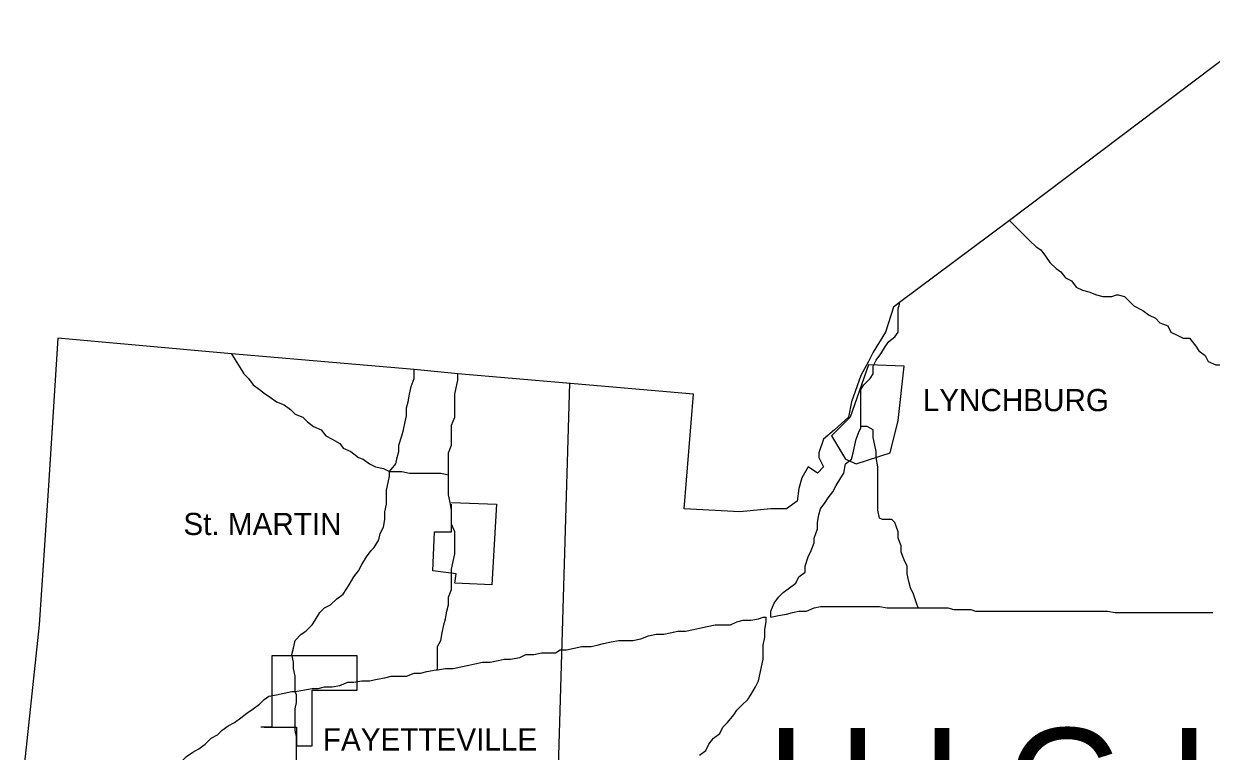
# Model space of a CAD drawing. Extents: x 0 to 34, y 0 to 22.
# Drawn here: x 2.524 to 3.569, y 18.392 to 19.032 of the extents above; entities that cross this region are included whole.
import ezdxf

# ---------------------------------------------------------------- set-up
doc = ezdxf.new("R2010")
doc.units = 0
doc.layers.add('Default', color=7, linetype='Continuous')
doc.layers.add('TR_Turning_Path1', color=7, linetype='Continuous')

msp = doc.modelspace()

# ---------------------------------------------------------------- linework, layer by layer
at = {"layer": 'Default'}
for points in [[(3.6203, 19.0319), (3.3913, 18.8587), (3.2945, 18.7865), (3.289, 18.7824), (3.2822, 18.7606), (3.2713, 18.7428), (3.2672, 18.7347), (3.2604, 18.7224), (3.2522, 18.6992), (3.2495, 18.6856), (3.2372, 18.6747), (3.2277, 18.6665), (3.2236, 18.6542), (3.2236, 18.6501), (3.2277, 18.6419), (3.2222, 18.6365), (3.214, 18.6419), (3.2086, 18.6324), (3.2059, 18.6229), (3.2045, 18.6119), (3.195, 18.6051), (3.1813, 18.6051), (3.1541, 18.6024), (3.105, 18.6051), (3.1132, 18.706), (3.0014, 18.7156)], [(3.3913, 18.8587), (3.3954, 18.8546), (3.4008, 18.8492), (3.4049, 18.8451), (3.409, 18.841), (3.4145, 18.8355), (3.4186, 18.8328), (3.4227, 18.8274), (3.4267, 18.8219), (3.4322, 18.8165), (3.4363, 18.8137), (3.4404, 18.8083), (3.4458, 18.8056), (3.4499, 18.8001), (3.4554, 18.7974), (3.4608, 18.796), (3.4676, 18.7933), (3.4731, 18.7919), (3.4813, 18.7919), (3.4854, 18.7933), (3.4867, 18.7933)], [(3.4867, 18.7933), (3.4922, 18.7919), (3.4976, 18.7865), (3.5004, 18.7837), (3.5085, 18.7796), (3.514, 18.7756), (3.5195, 18.7728), (3.5235, 18.7687), (3.5304, 18.766), (3.5331, 18.7606), (3.5385, 18.7578), (3.544, 18.7551), (3.5494, 18.7551), (3.5549, 18.7483), (3.5576, 18.7442), (3.5631, 18.7401), (3.5658, 18.7347), (3.5726, 18.7319), (3.5794, 18.7319), (3.5849, 18.7319), (3.5876, 18.7319), (3.589, 18.7319)], [(3.2604, 18.6774), (3.2604, 18.6828), (3.2604, 18.6897), (3.2604, 18.6965), (3.2604, 18.7019), (3.2604, 18.7101), (3.2631, 18.7142), (3.2686, 18.7197), (3.2713, 18.7237), (3.2713, 18.7306), (3.274, 18.736), (3.2781, 18.7415), (3.2822, 18.7483), (3.2849, 18.7524), (3.2904, 18.7565), (3.2931, 18.7606), (3.2931, 18.7674), (3.2931, 18.7756), (3.2931, 18.781), (3.2945, 18.7851), (3.2945, 18.7865)], [(2.5542, 18.7551), (2.546, 18.6256), (2.5378, 18.5029), (2.5255, 18.387), (2.5105, 18.2684), (2.5078, 18.2343), (2.4914, 18.0952), (2.4737, 17.9548), (2.456, 17.8075), (2.4014, 17.3603), (2.3783, 17.1694), (2.3551, 16.9827), (2.3115, 16.6009), (2.3074, 16.5723)], [(3.0014, 18.7156), (2.9059, 18.7237), (2.8677, 18.7278), (2.7069, 18.7415), (2.5542, 18.7551)], [(2.7069, 18.7415), (2.7109, 18.7347), (2.7137, 18.7306), (2.7178, 18.7237), (2.7219, 18.7197), (2.7259, 18.7142), (2.7314, 18.7101), (2.7369, 18.706), (2.7409, 18.7033), (2.7464, 18.6992), (2.7532, 18.6965), (2.7587, 18.6924), (2.7628, 18.6883), (2.7696, 18.6856), (2.7737, 18.6815), (2.7791, 18.6774), (2.7859, 18.6747), (2.79, 18.6692), (2.7955, 18.6665), (2.8023, 18.6624), (2.805, 18.6583), (2.8118, 18.6556), (2.8187, 18.6501), (2.8227, 18.6488), (2.8282, 18.6447), (2.8337, 18.6419), (2.8405, 18.6406), (2.8459, 18.6379)], [(2.8459, 18.6379), (2.8514, 18.6447), (2.8527, 18.6501), (2.8541, 18.6556), (2.8541, 18.661), (2.8568, 18.6692), (2.8582, 18.6747), (2.8596, 18.6815), (2.8609, 18.6869), (2.8609, 18.6938), (2.8623, 18.6992), (2.8636, 18.706), (2.865, 18.7128), (2.8677, 18.7197), (2.8677, 18.7251), (2.8677, 18.7278)], [(3.2468, 18.6488), (3.2563, 18.6447), (3.2863, 18.6542), (3.2931, 18.6828), (3.2986, 18.7306), (3.2672, 18.7319), (3.2509, 18.6856), (3.2345, 18.6692), (3.2468, 18.6488)], [(2.8977, 18.6351), (2.8977, 18.6419), (2.8977, 18.6474), (2.8977, 18.6542), (2.9005, 18.661), (2.9005, 18.6665), (2.9005, 18.6733), (2.9005, 18.6788), (2.9032, 18.6856), (2.9032, 18.6924), (2.9032, 18.6992), (2.9032, 18.706), (2.9046, 18.7115), (2.9059, 18.7183), (2.9059, 18.7237), (2.9059, 18.7237)], [(3.0041, 18.7156), (2.9836, 18.0202), (2.9659, 17.693), (3.3122, 17.6835), (3.514, 17.6848), (3.6258, 17.6807), (3.6694, 17.6794)], [(3.1813, 18.5097), (3.1813, 18.5151), (3.1841, 18.522), (3.1881, 18.5274), (3.1922, 18.5315), (3.1977, 18.5356), (3.2031, 18.5397), (3.2059, 18.5451), (3.2113, 18.5492), (3.2113, 18.5547), (3.214, 18.5629), (3.2168, 18.5683), (3.2195, 18.5751), (3.2195, 18.5792), (3.2222, 18.5874), (3.2222, 18.5929), (3.2236, 18.5997), (3.225, 18.6051), (3.229, 18.6106), (3.2318, 18.6147), (3.2359, 18.6201), (3.2386, 18.6256), (3.2427, 18.6324), (3.2454, 18.6365), (3.2468, 18.6447), (3.2522, 18.6488), (3.2536, 18.6542), (3.255, 18.661), (3.2563, 18.6665), (3.259, 18.6733), (3.2604, 18.676), (3.2604, 18.6774)], [(3.3109, 18.5179), (3.3095, 18.522), (3.3068, 18.5301), (3.304, 18.5356), (3.3027, 18.541), (3.3013, 18.5479), (3.3013, 18.5547), (3.2986, 18.5601), (3.2959, 18.567), (3.2959, 18.5724), (3.2931, 18.5792), (3.2931, 18.5847), (3.2904, 18.5929), (3.2877, 18.5956), (3.2795, 18.5956), (3.2768, 18.5969), (3.2754, 18.6038), (3.2754, 18.6106), (3.2754, 18.6174), (3.2754, 18.6242), (3.2754, 18.6297), (3.2754, 18.6365), (3.2754, 18.6419), (3.274, 18.6501), (3.274, 18.6556), (3.2727, 18.661), (3.2713, 18.6678), (3.2713, 18.6747), (3.2659, 18.6774), (3.2618, 18.6774), (3.2604, 18.6774)], [(2.7628, 18.4442), (2.7628, 18.4524), (2.7628, 18.4579), (2.7614, 18.4647), (2.7614, 18.4701), (2.76, 18.477), (2.7614, 18.4824), (2.7628, 18.4892), (2.7682, 18.4947), (2.7723, 18.4974), (2.7778, 18.5029), (2.7805, 18.507), (2.7846, 18.5138), (2.7887, 18.5179), (2.7941, 18.5206), (2.7996, 18.526), (2.805, 18.5301), (2.8077, 18.5342), (2.8105, 18.5383), (2.8146, 18.5451), (2.8187, 18.5506), (2.8214, 18.556), (2.8255, 18.5629), (2.8296, 18.5683), (2.8323, 18.571), (2.8364, 18.5779), (2.8377, 18.5833), (2.8405, 18.5888), (2.8418, 18.5956), (2.8418, 18.6024), (2.8432, 18.6092), (2.8432, 18.6174), (2.8432, 18.6215), (2.8446, 18.6283), (2.8459, 18.6338), (2.8459, 18.6379), (2.8459, 18.6379)], [(2.8459, 18.6379), (2.8514, 18.6379), (2.8568, 18.6379), (2.8636, 18.6365), (2.8705, 18.6365), (2.8773, 18.6365), (2.8841, 18.6365), (2.8909, 18.6365), (2.8977, 18.6351)], [(2.8882, 18.4633), (2.8882, 18.4701), (2.8882, 18.477), (2.8882, 18.4838), (2.8909, 18.4892), (2.8923, 18.4961), (2.8936, 18.5029), (2.895, 18.5083), (2.8964, 18.5151), (2.8977, 18.5206), (2.8977, 18.5274), (2.9005, 18.5342), (2.9005, 18.5397), (2.9005, 18.5465), (2.9005, 18.552), (2.9018, 18.5588), (2.9032, 18.5656), (2.9032, 18.571), (2.9032, 18.5792), (2.9032, 18.5847), (2.9005, 18.5915), (2.9005, 18.5956), (2.9005, 18.6038), (2.8991, 18.6106), (2.8977, 18.6174), (2.8977, 18.6242), (2.8977, 18.6283), (2.8977, 18.6351)], [(2.9005, 18.6106), (2.94, 18.6092), (2.9359, 18.5383), (2.9032, 18.5397), (2.9046, 18.5479), (2.8841, 18.5506), (2.8855, 18.5847), (2.9005, 18.5847), (2.9005, 18.6092)], [(3.1813, 18.5097), (3.1881, 18.5111), (3.195, 18.5124), (3.2004, 18.5138), (3.2059, 18.5151), (3.2127, 18.5151), (3.2195, 18.5179), (3.225, 18.5192), (3.2304, 18.5192), (3.2372, 18.5192), (3.244, 18.5192), (3.2509, 18.5192), (3.2563, 18.5192), (3.2631, 18.5192), (3.2713, 18.5192), (3.2768, 18.5192), (3.2836, 18.5179), (3.289, 18.5179), (3.2959, 18.5179), (3.3013, 18.5179), (3.3081, 18.5179), (3.3109, 18.5179)], [(3.3109, 18.5179), (3.3177, 18.5179), (3.3231, 18.5179), (3.3299, 18.5179), (3.3368, 18.5179), (3.3422, 18.5165), (3.3504, 18.5165), (3.3572, 18.5165), (3.3613, 18.5151), (3.3695, 18.5151), (3.3749, 18.5151), (3.3831, 18.5151), (3.3886, 18.5151), (3.394, 18.5151), (3.4022, 18.5151), (3.4077, 18.5151), (3.4145, 18.5151), (3.4213, 18.5151), (3.4267, 18.5151), (3.4336, 18.5151), (3.4404, 18.5151), (3.4458, 18.5151), (3.4526, 18.5151), (3.4595, 18.5151), (3.4676, 18.5151), (3.4731, 18.5151), (3.4772, 18.5151), (3.4772, 18.5151)], [(2.9959, 18.4811), (3.0014, 18.4811), (3.0082, 18.4824), (3.015, 18.4838), (3.0232, 18.4838), (3.0286, 18.4851), (3.0341, 18.4865), (3.0409, 18.4879), (3.0477, 18.4892), (3.0545, 18.4892), (3.06, 18.4892), (3.0668, 18.4906), (3.0736, 18.4933), (3.0804, 18.4947), (3.0872, 18.4947), (3.0927, 18.4961), (3.0995, 18.4974), (3.1063, 18.4974), (3.1132, 18.4988), (3.1186, 18.5001), (3.1254, 18.5015), (3.1322, 18.5029), (3.1377, 18.5029), (3.1459, 18.5029), (3.1513, 18.5056), (3.1568, 18.507), (3.1636, 18.507), (3.1704, 18.5083), (3.1745, 18.5097), (3.1772, 18.5097)], [(3.1186, 18.3883), (3.1241, 18.3924), (3.1268, 18.3979), (3.1309, 18.4033), (3.1363, 18.4074), (3.1391, 18.4129), (3.1431, 18.417), (3.1486, 18.4238), (3.1513, 18.4279), (3.1554, 18.432), (3.1609, 18.4374), (3.1636, 18.4415), (3.1677, 18.4483), (3.1704, 18.4538), (3.1718, 18.4606), (3.1731, 18.4661), (3.1745, 18.4729), (3.1745, 18.4783), (3.1745, 18.4851), (3.1759, 18.492), (3.1759, 18.4988), (3.1772, 18.5056), (3.1772, 18.5083), (3.1772, 18.5097)], [(3.4772, 18.5151), (3.484, 18.5138), (3.4922, 18.5138), (3.499, 18.5138), (3.5058, 18.5138), (3.5113, 18.5138), (3.5167, 18.5138), (3.5235, 18.5138), (3.5304, 18.5138), (3.5385, 18.5138), (3.5426, 18.5138), (3.5494, 18.5138), (3.5563, 18.5138), (3.5631, 18.5138), (3.5699, 18.5138)], [(2.7355, 18.4129), (2.7641, 18.4129), (2.7641, 18.3965), (2.7778, 18.3965), (2.7778, 18.4456), (2.8173, 18.4456), (2.8173, 18.4756), (2.7423, 18.4756), (2.7423, 18.4129), (2.7328, 18.4129)], [(2.8882, 18.4633), (2.895, 18.4647), (2.9018, 18.4647), (2.9086, 18.4661), (2.9155, 18.4674), (2.9209, 18.4688), (2.9277, 18.4701), (2.9345, 18.4701), (2.9414, 18.4715), (2.9468, 18.4729), (2.9523, 18.4729), (2.9605, 18.4742), (2.9659, 18.477), (2.9727, 18.477), (2.9795, 18.4783), (2.985, 18.4783), (2.9918, 18.4783), (2.9959, 18.4811)], [(2.7628, 18.4442), (2.7696, 18.4456), (2.7778, 18.447), (2.7832, 18.447), (2.7887, 18.4483), (2.7955, 18.4483), (2.8023, 18.4497), (2.8091, 18.4524), (2.8146, 18.4524), (2.8214, 18.4538), (2.8282, 18.4538), (2.835, 18.4552), (2.8418, 18.4565), (2.8473, 18.4579), (2.8541, 18.4579), (2.8609, 18.4579), (2.8677, 18.4606), (2.8732, 18.4606), (2.8786, 18.462), (2.8868, 18.4633), (2.8882, 18.4633)], [(2.6578, 18.3788), (2.6632, 18.3829), (2.6673, 18.387), (2.6728, 18.3911), (2.6782, 18.3938), (2.6837, 18.3979), (2.6891, 18.4033), (2.6946, 18.4061), (2.6987, 18.4102), (2.7041, 18.4142), (2.7096, 18.417), (2.715, 18.4211), (2.7205, 18.4252), (2.7259, 18.4292), (2.7314, 18.4333), (2.7355, 18.4374), (2.7396, 18.4402), (2.7464, 18.4415), (2.7532, 18.4429), (2.76, 18.4442), (2.7628, 18.4442)], [(2.7628, 18.3256), (2.7628, 18.3338), (2.7628, 18.3393), (2.7628, 18.3474), (2.7628, 18.3529), (2.7628, 18.3597), (2.7628, 18.3665), (2.7628, 18.372), (2.7641, 18.3802), (2.7641, 18.3856), (2.7641, 18.3911), (2.7641, 18.3979), (2.7641, 18.4047), (2.7628, 18.4102), (2.7628, 18.4156), (2.7628, 18.4238), (2.7628, 18.4292), (2.7641, 18.4347), (2.7641, 18.4415), (2.7628, 18.4442)]]:
    msp.add_lwpolyline(points, dxfattribs=at)

# ---------------------------------------------------------------- texts
for s, height, p in [('LYNCHBURG', 0.0195, (3.3149, 18.691)), ('St. MARTIN', 0.0195, (2.6646, 18.582)), ('FAYETTEVILLE', 0.019502, (2.7873, 18.3924))]:
    msp.add_text(s, height=height, dxfattribs=at).set_placement(p)
at = {"layer": 'TR_Turning_Path1'}
msp.add_text('H I G H L A N D', height=0.101489, dxfattribs=at).set_placement((3.1772, 18.3106))

doc.saveas('drawing.dxf')
